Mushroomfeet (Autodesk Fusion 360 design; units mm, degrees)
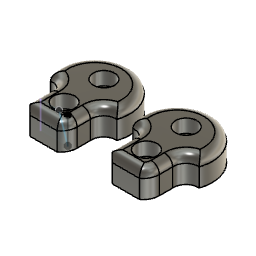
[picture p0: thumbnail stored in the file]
sketch "Sketch1" plane through (0, 0, 0) normal (0, 0, 1) x axis (1, 0, 0)
  line L1 (-7.5182, -15) -> (-17.7456, -15)
  line L2 (-20, -5) -> (-20, -10.9164)
  line L3 (-5, -5) -> (-5, -10)
  arc A1 centre (-12.5, 4.1667) radius 13.1762 clockwise from (-25, 0) to (0, 0)
  arc A2 centre (-11.223, -10) radius 6.223 clockwise from (-5, -10) to (-7.5182, -15)
  arc A3 centre (-24.4348, -4.4348) radius 4.4707 clockwise from (-25, 0) to (-20, -5)
  arc A4 centre (-0.3795, -4.6205) radius 4.6361 clockwise from (-5, -5) to (0, 0)
  arc A5 centre (-14.0927, -10.3193) radius 5.9374 clockwise from (-17.7456, -15) to (-20, -10.9164)
  point P1 (0, 0)
  point P3 (0, 0)
  point P13 (0, 0)
  coincident P1 P3
  horizontal L1
  tangent L3 A2
  coincident P1 P13
extrude "Extrude1" new body sketch "Sketch1" profile of A1 L1 L2 L3 A2 A3 A4 along normal blind 10
sketch "Sketch2" plane through (0, -15, 0) normal (0, -1, 0) x axis (1, 0, 0)
  line L1 (-7.5182, 0) -> (-17.7456, 0)
  line L2 (-7.5182, 10) -> (-7.5182, 0)
  line L3 (-17.7456, 10) -> (-7.5182, 10)
  line L4 (-7.5182, 0) -> (-10.8323, 10)
  line L5 (-10.8323, 10) -> (-7.5182, 10)
  line L6 (-7.5182, 0) -> (-7.5182, 10)
  line L7 (-7.5182, 10) -> (-10.8323, 10)
  line L8 (-17.7456, 0) -> (-17.7456, 10)
  point P6 (-10.8323, 10)
  point P3 (-7.5182, 0)
  point P7 (-7.5182, 0)
  point P4 (-7.5182, 10)
  point P8 (-7.5182, 10)
  coincident L3 P6
  coincident P3 P7
  coincident P4 P8
  perpendicular L2 L5
fillet "Fillet1" radius 3.1
hole "Hole1" HoleDepth 15 HoleDiameter 6 TipAngle 180 CBDepth 5 CBDiameter 8
rectangular_pattern "R-Pattern1" uSpaceDistance -15 vSpaceDistance 0
rectangular_pattern "R-Pattern2" uSpaceDistance 31 vSpaceDistance 0
move "Move2"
